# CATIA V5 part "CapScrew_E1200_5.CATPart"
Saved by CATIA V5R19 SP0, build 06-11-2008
Part number: CapScrew_E1200_5
Nomenclature: E 1200/5x25
Source: Unknown
Description: MEUSBURGER
Bounding box of the stored display mesh (mm): x -4.249 to 4.25, y -4.25 to 4.245, z 0 to 30
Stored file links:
  C:\Users\jsmid\Desktop\DP_Smidak_Forma LEGO\CapScrew_E1200_5.CATPart
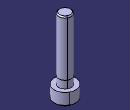
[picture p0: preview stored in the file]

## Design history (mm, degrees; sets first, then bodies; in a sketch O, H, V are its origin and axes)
Body1 (main body)
  Solid1 "PartBody": solid without history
